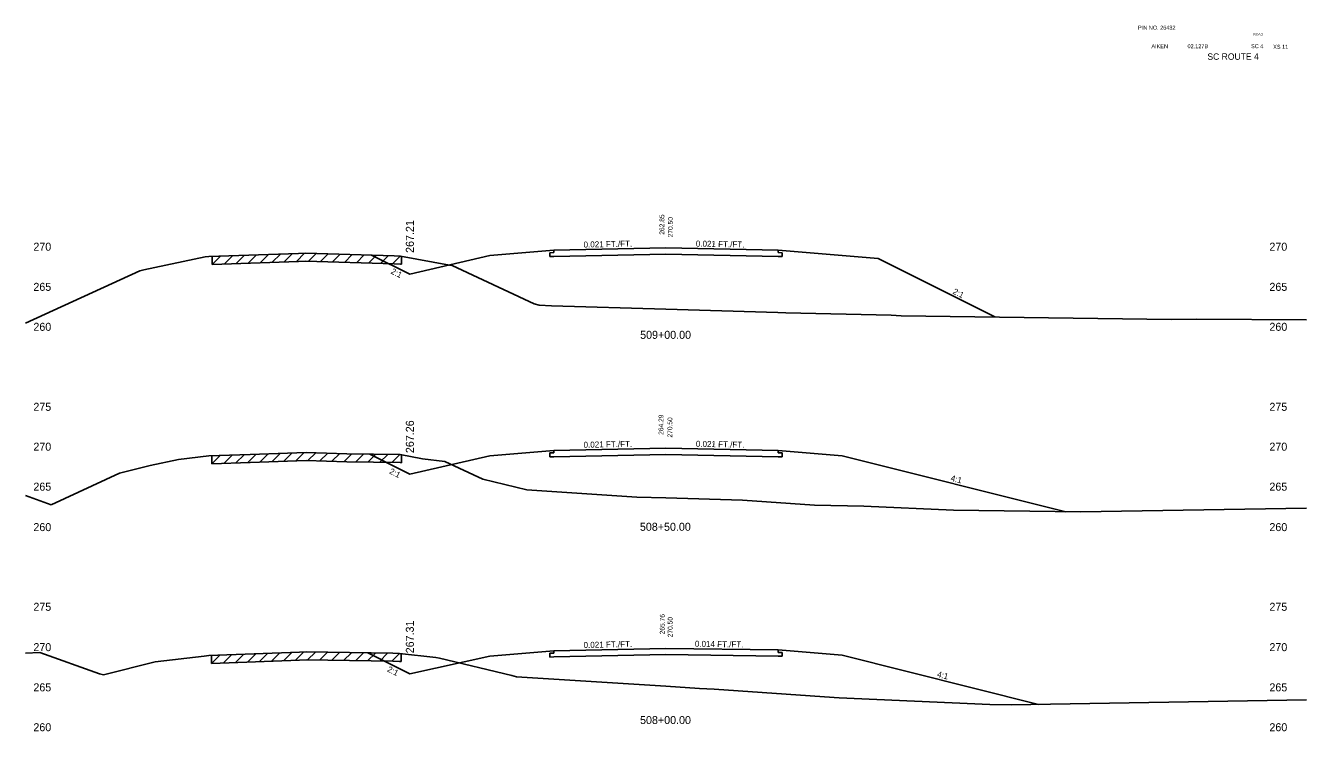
# Model space of a CAD drawing. Extents: x 883 to 1160, y 1002 to 4323.
# Drawn here: x 1000 to 1160, y 2165.1 to 2253.3 of the extents above; entities that cross this region are included whole.
import ezdxf

# ---------------------------------------------------------------- set-up
doc = ezdxf.new("R2010")
doc.units = 0
for name, color, linetype in [('Level 1', 7, 'Continuous'), ('Level 10', 7, 'Continuous'), ('Level 11', 7, 'Continuous'), ('Level 12', 7, 'Continuous'), ('Level 3', 7, 'Continuous'), ('Level 32', 7, 'Continuous'), ('Level 33', 7, 'Continuous'), ('Level 59', 7, 'Continuous'), ('Level 6', 7, 'Continuous'), ('Level 60', 7, 'Continuous'), ('Level 61', 7, 'Continuous'), ('Level 7', 7, 'Continuous')]:
    doc.layers.add(name, color=color, linetype=linetype)

msp = doc.modelspace()

# ---------------------------------------------------------------- linework, layer by layer
at = {"layer": 'Level 11'}
for p, q in [((1066, 2224.91), (1065.5, 2224.9)), ((1065.5, 2224.9), (1065.5, 2224.42)), ((1065.5, 2224.42), (1066, 2224.43)), ((1066, 2225.21), (1066, 2224.91)), ((1094, 2224.91), (1094, 2225.21)), ((1094.5, 2224.9), (1094, 2224.91)), ((1094, 2224.43), (1094.5, 2224.42)), ((1094.5, 2224.42), (1094.5, 2224.9)), ((1066, 2200.21), (1066, 2199.91)), ((1094, 2199.91), (1094, 2200.21)), ((1066, 2199.91), (1065.5, 2199.9)), ((1065.5, 2199.9), (1065.5, 2199.42)), ((1065.5, 2199.42), (1066, 2199.43)), ((1094.5, 2199.9), (1094, 2199.91)), ((1094, 2199.43), (1094.5, 2199.42)), ((1094.5, 2199.42), (1094.5, 2199.9)), ((1066, 2174.91), (1065.5, 2174.9)), ((1065.5, 2174.9), (1065.5, 2174.42)), ((1065.5, 2174.42), (1066, 2174.43)), ((1066, 2175.21), (1066, 2174.91)), ((1094, 2175), (1094, 2175.3)), ((1094.5, 2174.99), (1094, 2175)), ((1094, 2174.52), (1094.5, 2174.51)), ((1094.5, 2174.51), (1094.5, 2174.99))]:
    msp.add_line(p, q, dxfattribs=at)
at = {"layer": 'Level 12'}
for p, q in [((1080, 2224.72), (1066, 2224.43)), ((1094, 2224.43), (1080, 2224.72)), ((1080, 2199.72), (1066, 2199.43)), ((1094, 2199.43), (1080, 2199.72)), ((1080, 2174.72), (1066, 2174.43)), ((1094, 2174.52), (1080, 2174.72))]:
    msp.add_line(p, q, dxfattribs=at)
at = {"layer": 'Level 59'}
for p, q in [((1066, 2225.21), (1080, 2225.5)), ((1080, 2225.5), (1094, 2225.21)), ((1066, 2200.21), (1080, 2200.5)), ((1080, 2200.5), (1094, 2200.21)), ((1066, 2175.21), (1080, 2175.5)), ((1080, 2175.5), (1094, 2175.3))]:
    msp.add_line(p, q, dxfattribs=at)
at = {"layer": 'Level 6'}
for p, q in [((1058, 2224.54), (1066, 2225.21)), ((1094, 2225.21), (1106.5, 2224.17)), ((1058, 2199.54), (1066, 2200.21)), ((1094, 2200.21), (1102, 2199.54)), ((1058, 2174.54), (1066, 2175.21)), ((1094, 2175.3), (1102, 2174.63))]:
    msp.add_line(p, q, dxfattribs=at)
at = {"layer": 'Level 60'}
for p, q in [((1014.76, 2222.77), (1022.41, 2224.37)), ((1022.41, 2224.37), (1022.9, 2224.42)), ((1022.9, 2224.42), (1034.11, 2224.82)), ((1034.11, 2224.82), (1035, 2224.86)), ((1035, 2224.86), (1046.04, 2224.5)), ((1046.04, 2224.5), (1046.85, 2224.49)), ((1046.85, 2224.49), (1052.97, 2223.36)), ((1000, 2216.09), (1014.26, 2222.65)), ((1014.26, 2222.65), (1014.76, 2222.77)), ((1052.97, 2223.36), (1053.3, 2223.32)), ((1053.3, 2223.32), (1063.53, 2218.5)), ((1063.53, 2218.5), (1064.15, 2218.35)), ((1064.15, 2218.35), (1065.69, 2218.25)), ((1065.69, 2218.25), (1080, 2217.85)), ((1080, 2217.85), (1093.99, 2217.45)), ((1093.99, 2217.45), (1094.99, 2217.38)), ((1094.99, 2217.38), (1108.12, 2217.1)), ((1108.12, 2217.1), (1109.36, 2217.04)), ((1109.36, 2217.04), (1143.14, 2216.57)), ((1143.14, 2216.57), (1146.33, 2216.62)), ((1146.33, 2216.62), (1160, 2216.51)), ((1015.57, 2198.34), (1019.1, 2199.07)), ((1019.1, 2199.07), (1022.88, 2199.52)), ((1022.88, 2199.52), (1028.06, 2199.71)), ((1028.06, 2199.71), (1035.03, 2199.97)), ((1035.03, 2199.97), (1040.12, 2199.8)), ((1040.12, 2199.8), (1046.77, 2199.69)), ((1046.77, 2199.69), (1049.6, 2199.17)), ((1049.6, 2199.17), (1052.38, 2198.85)), ((1052.38, 2198.85), (1057.11, 2196.62)), ((1003.18, 2193.44), (1011.73, 2197.37)), ((1011.73, 2197.37), (1015.57, 2198.34)), ((1057.11, 2196.62), (1062.62, 2195.29)), ((1062.62, 2195.29), (1076.37, 2194.39)), ((1000, 2194.57), (1003.18, 2193.44)), ((1076.37, 2194.39), (1080, 2194.29)), ((1080, 2194.29), (1089.57, 2194.02)), ((1089.57, 2194.02), (1098.56, 2193.4)), ((1098.56, 2193.4), (1104.71, 2193.26)), ((1104.71, 2193.26), (1115.91, 2192.76)), ((1115.91, 2192.76), (1131.77, 2192.54)), ((1131.77, 2192.54), (1160, 2193.01)), ((1000, 2174.92), (1001.79, 2175)), ((1001.79, 2175), (1009.23, 2172.3)), ((1016.18, 2173.8), (1022.31, 2174.54)), ((1022.31, 2174.54), (1022.89, 2174.62)), ((1022.89, 2174.62), (1034.21, 2175.03)), ((1034.21, 2175.03), (1035.05, 2175.05)), ((1035.05, 2175.05), (1045.88, 2174.88)), ((1045.88, 2174.88), (1046.72, 2174.87)), ((1046.72, 2174.87), (1051.26, 2174.35)), ((1009.71, 2172.19), (1016.18, 2173.8)), ((1051.26, 2174.35), (1051.7, 2174.29)), ((1051.7, 2174.29), (1060.76, 2172.1)), ((1009.23, 2172.3), (1009.71, 2172.19)), ((1060.76, 2172.1), (1061.32, 2171.96)), ((1061.32, 2171.96), (1080, 2170.76)), ((1080, 2170.76), (1084.18, 2170.49)), ((1084.18, 2170.49), (1086.01, 2170.4)), ((1086.01, 2170.4), (1101.01, 2169.36)), ((1101.01, 2169.36), (1101.62, 2169.33)), ((1101.62, 2169.33), (1120.46, 2168.48)), ((1120.46, 2168.48), (1123.1, 2168.44)), ((1123.1, 2168.44), (1160, 2169.08))]:
    msp.add_line(p, q, dxfattribs=at)
at = {"layer": 'Level 61'}
for p, q in [((1024.35, 2224.48), (1023.32, 2223.44)), ((1023.32, 2224.44), (1023.32, 2223.44)), ((1025.85, 2224.53), (1024.82, 2223.49)), ((1027.35, 2224.58), (1026.32, 2223.55)), ((1028.85, 2224.64), (1027.82, 2223.6)), ((1030.35, 2224.69), (1029.32, 2223.65)), ((1031.85, 2224.74), (1030.82, 2223.71)), ((1033.35, 2224.8), (1032.32, 2223.76)), ((1034.85, 2224.85), (1033.82, 2223.81)), ((1036.28, 2224.82), (1035.32, 2223.85)), ((1037.78, 2224.77), (1036.82, 2223.8)), ((1039.28, 2224.72), (1038.32, 2223.75)), ((1040.78, 2224.67), (1039.82, 2223.7)), ((1042.28, 2224.62), (1041.32, 2223.65)), ((1043.78, 2224.57), (1042.82, 2223.61)), ((1045.28, 2224.53), (1044.32, 2223.56)), ((1046.8, 2224.49), (1045.82, 2223.51)), ((1046.97, 2223.47), (1046.97, 2224.47)), ((1023.32, 2223.44), (1034.11, 2223.82)), ((1034.11, 2223.82), (1035, 2223.86)), ((1035, 2223.86), (1046.04, 2223.5)), ((1046.04, 2223.5), (1046.85, 2223.49)), ((1046.85, 2223.49), (1046.97, 2223.47)), ((1024.31, 2199.58), (1023.27, 2198.54)), ((1023.27, 2199.54), (1023.27, 2198.54)), ((1023.27, 2198.54), (1028.06, 2198.71)), ((1025.81, 2199.63), (1024.77, 2198.59)), ((1027.31, 2199.68), (1026.27, 2198.65)), ((1028.81, 2199.74), (1027.77, 2198.7)), ((1028.06, 2198.71), (1035.03, 2198.97)), ((1030.31, 2199.79), (1029.27, 2198.75)), ((1031.81, 2199.85), (1030.77, 2198.81)), ((1033.31, 2199.9), (1032.27, 2198.86)), ((1034.81, 2199.96), (1033.77, 2198.92)), ((1035.03, 2198.97), (1040.12, 2198.8)), ((1036.24, 2199.93), (1035.27, 2198.96)), ((1037.74, 2199.88), (1036.77, 2198.91)), ((1039.24, 2199.83), (1038.27, 2198.86)), ((1040.75, 2199.79), (1039.77, 2198.81)), ((1040.12, 2198.8), (1046.77, 2198.69)), ((1042.26, 2199.77), (1041.27, 2198.78)), ((1043.76, 2199.74), (1042.77, 2198.76)), ((1045.26, 2199.72), (1044.27, 2198.73)), ((1046.76, 2199.69), (1045.77, 2198.71)), ((1046.77, 2198.69), (1046.95, 2198.66)), ((1046.95, 2198.66), (1046.95, 2199.66)), ((1024.27, 2174.67), (1023.23, 2173.63)), ((1023.23, 2174.63), (1023.23, 2173.63)), ((1025.77, 2174.72), (1024.73, 2173.68)), ((1027.27, 2174.78), (1026.23, 2173.74)), ((1028.77, 2174.83), (1027.73, 2173.79)), ((1030.27, 2174.89), (1029.23, 2173.85)), ((1031.77, 2174.94), (1030.73, 2173.9)), ((1033.27, 2175), (1032.23, 2173.96)), ((1034.76, 2175.05), (1033.73, 2174.02)), ((1036.22, 2175.03), (1035.23, 2174.05)), ((1037.72, 2175.01), (1036.73, 2174.02)), ((1039.22, 2174.98), (1038.23, 2174)), ((1040.72, 2174.96), (1039.73, 2173.98)), ((1042.22, 2174.94), (1041.23, 2173.95)), ((1043.72, 2174.91), (1042.73, 2173.93)), ((1045.22, 2174.89), (1044.23, 2173.9)), ((1046.72, 2174.87), (1045.73, 2173.88)), ((1046.93, 2173.85), (1046.93, 2174.85)), ((1023.23, 2173.63), (1034.21, 2174.03)), ((1034.21, 2174.03), (1035.05, 2174.05)), ((1035.05, 2174.05), (1045.88, 2173.88)), ((1045.88, 2173.88), (1046.72, 2173.87)), ((1046.72, 2173.87), (1046.93, 2173.85))]:
    msp.add_line(p, q, dxfattribs=at)
at = {"layer": 'Level 7'}
for p, q in [((1043.23, 2224.59), (1048, 2222.21)), ((1048, 2222.21), (1058, 2224.54)), ((1106.5, 2224.17), (1121.08, 2216.88)), ((1043, 2199.76), (1048, 2197.26)), ((1048, 2197.26), (1058, 2199.54)), ((1102, 2199.54), (1129.93, 2192.56)), ((1042.76, 2174.93), (1048, 2172.31)), ((1048, 2172.31), (1058, 2174.54)), ((1102, 2174.63), (1126.53, 2168.5))]:
    msp.add_line(p, q, dxfattribs=at)

# ---------------------------------------------------------------- texts
at = {"layer": 'Level 1'}
for s, height, p in [('PIN NO. 26432', 0.5, (1138.97, 2252.75)), ('AIKEN', 0.5, (1140.64, 2250.44)), ('02.127B', 0.5, (1145.15, 2250.44)), ('SC ROUTE 4', 0.8, (1147.63, 2248.99)), ('SC 4', 0.5, (1153.09, 2250.44)), ('XS 11', 0.5, (1155.85, 2250.36)), ('509+00.00', 1, (1076.77, 2214.15)), ('508+50.00', 1, (1076.74, 2190.18)), ('508+00.00', 1, (1076.76, 2166.05))]:
    msp.add_text(s, height=height, dxfattribs=at).set_placement(p)
at = {"layer": 'Level 10'}
for s, p in [('262.85', (1079.79, 2227.15)), ('264.29', (1079.67, 2202.16)), ('265.76', (1079.83, 2177.25))]:
    msp.add_text(s, height=0.6, rotation=90, dxfattribs=at).set_placement(p)
at = {"layer": 'Level 3'}
for s, height, p in [('ROAD', 0.3, (1153.38, 2252.02)), (' 270', 1, (1000.6, 2225.15)), (' 270', 1, (1155.01, 2225.15)), (' 265', 1, (1000.6, 2220.14)), (' 265', 1, (1155.01, 2220.14)), (' 260', 1, (1000.6, 2215.15)), (' 260', 1, (1155.01, 2215.15)), (' 275', 1, (1000.6, 2205.16)), (' 275', 1, (1155.01, 2205.16)), (' 270', 1, (1000.6, 2200.18)), (' 270', 1, (1155.01, 2200.18)), (' 265', 1, (1000.6, 2195.19)), (' 265', 1, (1155.01, 2195.19)), (' 260', 1, (1000.6, 2190.14)), (' 260', 1, (1155.01, 2190.14)), (' 275', 1, (1000.6, 2180.19)), (' 275', 1, (1155.01, 2180.19)), (' 270', 1, (1000.6, 2175.15)), (' 270', 1, (1155.01, 2175.15)), (' 265', 1, (1000.6, 2170.13)), (' 265', 1, (1155.01, 2170.13)), (' 260', 1, (1000.6, 2165.15)), (' 260', 1, (1155.01, 2165.15))]:
    msp.add_text(s, height=height, dxfattribs=at).set_placement(p)
at = {"layer": 'Level 32'}
for s, rotation, p in [('0.021 FT./FT.', 1.1916, (1069.71, 2225.54)), ('0.021 FT./FT.', 358.8084, (1083.72, 2225.67)), ('2:1', 333.435, (1045.55, 2222.34)), ('2:1', 333.435, (1115.75, 2219.82)), ('0.021 FT./FT.', 1.1916, (1069.71, 2200.54)), ('0.021 FT./FT.', 358.8084, (1083.72, 2200.67)), ('2:1', 333.435, (1045.36, 2197.37)), ('4:1', 345.9638, (1115.51, 2196.42)), ('0.021 FT./FT.', 1.1916, (1069.71, 2175.54)), ('0.014 FT./FT.', 359.1793, (1083.6, 2175.7)), ('2:1', 333.435, (1045.1, 2172.65)), ('4:1', 345.9638, (1113.81, 2171.94))]:
    msp.add_text(s, height=0.75, rotation=rotation, dxfattribs=at).set_placement(p)
at = {"layer": 'Level 33'}
for s, p in [('267.21', (1048.5, 2224.88)), ('267.26', (1048.5, 2199.88)), ('267.31', (1048.5, 2174.88))]:
    msp.add_text(s, height=1, rotation=90, dxfattribs=at).set_placement(p)
at = {"layer": 'Level 59'}
for p in [(1080.85, 2226.59), (1080.79, 2201.59), (1080.82, 2176.65)]:
    msp.add_text(' 270.50', height=0.6, rotation=90, dxfattribs=at).set_placement(p)

doc.saveas('drawing.dxf')
